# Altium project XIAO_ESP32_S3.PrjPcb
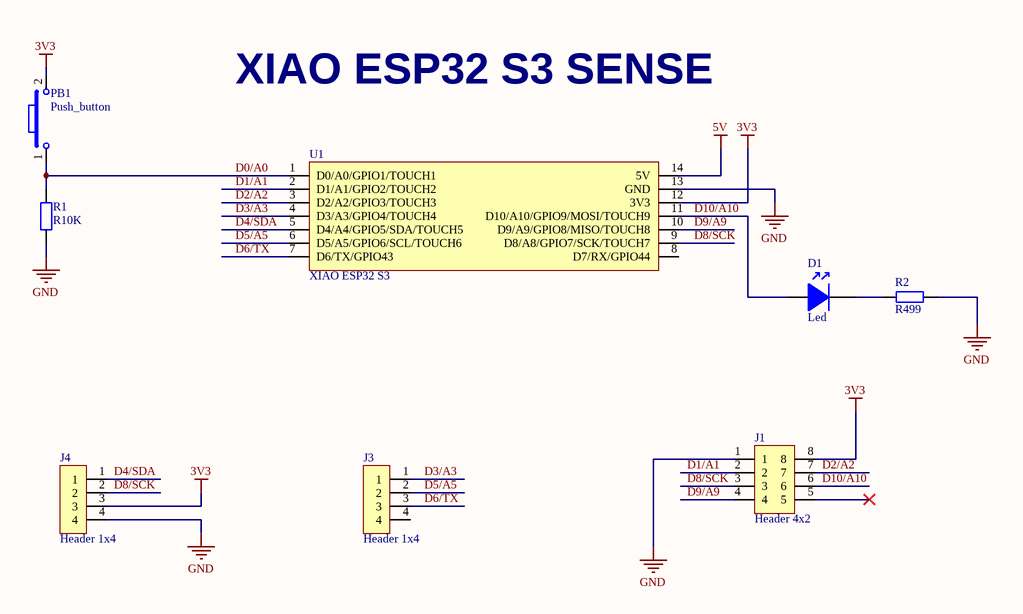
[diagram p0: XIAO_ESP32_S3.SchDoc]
1 sheet, 8 parts. Net scope: global (net labels, ports and power ports of the same name join across sheets).
Board file: XIAO_ESP32_S3.PcbDoc

## Sheet XIAO_ESP32_S3.SchDoc
size A4; SheetNumber: 1; SheetTotal: 1

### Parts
D1  Led  [LED1206]
J1  Header 4x2  [HDR4X2_FEMALE]
J3  Header 1x4  [HDR4X1_FEMALE]
J4  Header 1x4  [HDR4X1_FEMALE]
PB1  Push_button  [6x3x2.5mm SMD]
R1  R10K  [RES1206]
R2  R499  [RES1206]
U1  XIAO ESP32 S3  [XIAO_ESP32_S3]

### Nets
3V3: J1.8 J4.3 PB1.2 U1.12(3V3)
5V: U1.14(5V)
GND: J1.1 J4.4 R1.1 R2.2 U1.13(GND)
D0/A0: PB1.1 R1.2 U1.1(D0/A0/GPIO1/TOUCH1)
D1/A1: J1.2 U1.2(D1/A1/GPIO2/TOUCH2)
D2/A2: J1.7 U1.3(D2/A2/GPIO3/TOUCH3)
D3/A3: J3.1 U1.4(D3/A3/GPIO4/TOUCH4)
D4/SDA: J4.1 U1.5(D4/A4/GPIO5/SDA/TOUCH5)
D5/A5: J3.2 U1.6(D5/A5/GPIO6/SCL/TOUCH6)
D6/TX: J3.3 U1.7(D6/TX/GPIO43)
D8/SCK: J1.3 J4.2 U1.9(D8/A8/GPIO7/SCK/TOUCH7)
D9/A9: J1.4 U1.10(D9/A9/GPIO8/MISO/TOUCH8)
D10/A10: D1.2 J1.6 U1.11(D10/A10/GPIO9/MOSI/TOUCH9)
NetD1_1: D1.1 R2.1

Not connected (* = marked no-connect by the designer): J1 5*; J3 4; U1 8(D7/RX/GPIO44)

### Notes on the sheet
- XIAO ESP32 S3 SENSE

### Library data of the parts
D1 = Led: 1206
PB1 = Push_button: PTS636SM25FSMTR LFS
